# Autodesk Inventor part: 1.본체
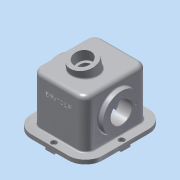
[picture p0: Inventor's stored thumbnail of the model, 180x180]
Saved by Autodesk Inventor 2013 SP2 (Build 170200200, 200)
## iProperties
Created: 2014-11
Part Number: 1.본체
Material: 알루미늄 6061
Document SubType Name: Modeling
Designer: dgall
Density: 2.71 g/cm^3
Mass: 2882.1 g
Surface Area: 2079.78 cm^2
Volume: 1063.5 cm^3
Author: dgall
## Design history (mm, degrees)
sketch "스케치1"
  geometry: L1 (-87, 98)-(87, 98); L2 (87, 98)-(87, -98); L3 (87, -98)-(-87, -98); L4 (-87, -98)-(-87, 98); 3 further points
  constraints: 8 end point, 2 midpoint, 2 parallel, 1 horizontal, 1 horizontal alignment, 1 perpendicular, 1 vertical alignment
  dimensions: "d0" = 196 distance of L1.end L2.end; "d2" = 174 distance of L2.end L3.end
extrude "돌출1" new body sketch "스케치1" distance "d3" = 10; taper "d4" = 0 deg
sketch "스케치2"
  geometry: L1 (65, -0.8)-(65, 118); L2 (65, 118)-(-65, 118); L3 (-65, 118)-(-65, -0.8); L4 (-87, 0)-(87, 0) reference; L5 (-65, -0.8)-(65, -0.8); 3 further points
  constraints: 8 end point, 2 midpoint, 2 perpendicular, 1 parallel, 1 vertical, 1 vertical alignment
  dimensions: "d5" = 130 distance of L1.end L2.end; "d7" = 118 distance between parallel lines of L2 L4
extrude "돌출2" join sketch "스케치2" stored distance "d8" = 152; taper "d9" = 0 deg
node "작업 평면2"
sketch "스케치4"
  geometry: L1 (98, 0)-(-98, 0) reference; L2 (98, -10)-(-98, -10) reference; C1 r 45.5 at (0, 58); 2 further points
  constraints: 2 vertical alignment, 1 centre point, 1 midpoint
  dimensions: "d11" = 68 distance from line of C1.centre L2; "d12" = 91 diameter of C1
extrude "돌출3" join sketch "스케치4" stored distance "d13" = 152; taper "d14" = 0 deg
node "작업 평면3"
sketch "스케치5"
  geometry: L1 (-98, -10)-(98, -10) reference; L2 (-98, 0)-(98, 0) reference; L3 (-66, -10)-(-66, 108); L4 (-66, 108)-(66, 108); L5 (66, 108)-(66, -10); L6 (76, 0)-(76, 118) reference; L7 (76, 118)-(-76, 118) reference; 3 further points
  constraints: 6 end point, 2 midpoint, 2 perpendicular, 2 point on line, 1 horizontal, 1 parallel, 1 vertical alignment
  dimensions: "d16" = 10 distance between parallel lines of L6 L5; "d17" = 10 distance between parallel lines of L7 L4
extrude "돌출4" cut sketch "스케치5" stored distance "d18" = 110; taper "d19" = 0 deg
sketch "스케치6"
  geometry: L1 (55, 108)-(55, -10) reference; L2 (-55, -10)-(55, -10) reference; L3 (55, 103.5)-(45, 93.5); L4 (45, 93.5)-(45, 58); L5 (45, 58)-(55, 58); 1 further point
  constraints: 6 end point, 2 point on line, 1 horizontal, 1 perpendicular
  dimensions: "d31" = 68 distance between parallel lines of L5 L2; "d32" = 71 diameter of L3.end L5; "d33" = 91 diameter of L3.start L5; "d34" = 10 horizontal distance of L3.start L3.end
revolve "회전1" sketch "스케치6" stored, may be unused: angle "d35" = 90 deg
sketch "스케치7"
  geometry: C1 r 45.5 at (0, 0) reference; C2 r 26 at (0, 0); 1 further point
  constraints: 1 centre point, 1 coincident
  dimensions: "d36" = 52 diameter of C2
extrude "돌출5" cut sketch "스케치7" stored distance "d38" = 110; taper "d39" = 0 deg
node "작업 평면4"
node "작업 평면6"
  node "작업 평면5"
sketch "스케치8"
  geometry: L1 (0, -45.5)-(0, 45.5) reference; L2 (164, -107.917)-(-10, -107.917) reference; C1 r 31 at (77, 0); 3 further points
  constraints: 2 midpoint, 1 centre point, 1 coincident, 1 horizontal alignment, 1 vertical alignment
  dimensions: "d42" = 62 diameter of C1
extrude "돌출6" join sketch "스케치8" stored distance "d44" = 110; taper "d45" = 0 deg
sketch "스케치9"
  geometry: C1 r 31 at (0, 0) reference; C2 r 21 at (0, 0)
  constraints: 1 centre point, 1 coincident
  dimensions: "d46" = 42 diameter of C2
extrude "돌출7" cut sketch "스케치9" distance "d48" = 25; taper "d49" = 0 deg
sketch "스케치10"
  geometry: C1 r 21 at (0, 0) reference; C2 r 15 at (0, 0)
  constraints: 1 centre point, 1 coincident
  dimensions: "d50" = 30 diameter of C2
extrude "돌출8" cut sketch "스케치10" stored distance "d52" = 25; taper "d53" = 0 deg
node "작업 평면7"
sketch "스케치11"
  geometry: C1 r 26 at (0, 0) reference; C2 r 45.5 at (0, 0) reference; A1 r 35 centre (0, 0) between (35, 0) and (0, 35); 3 further points
  constraints: 4 point on circle, 2 horizontal alignment, 2 vertical alignment, 1 centre point, 1 coincident
  dimensions: "d54" = 70 diameter of A1
hole "구멍1" sketch "스케치11" at (35, 0), (0, 35), (0, -35), (-35, 0) diameter "d56" = 3.242; stored, may be unused: countersink angle "d60" = 90 deg, drill point angle "d62" = 118 deg; dims "d57" = 13, "d58" = 4, "d59" = 2, "d61" = 16
node "작업 평면8"
sketch "스케치12"
  geometry: L1 (87, 98)-(-87, 98) reference; L2 (87, -98)-(87, 98) reference; L3 (11, 98)-(11, 78); L4 (11, 78)-(-11, 78); L5 (-11, 78)-(-11, 98); 2 further points
  constraints: 6 end point, 2 perpendicular, 2 point on line, 1 midpoint, 1 parallel, 1 vertical alignment
  dimensions: "d64" = 20 distance of L4.end L5.end; "d66" = 22 distance of L3.end L4.end
extrude "돌출9" join sketch "스케치12" distance "d67" = 5; taper "d68" = 0 deg
sketch "스케치13"
  geometry: L1 (-87, 98)-(-87, -98) reference; L2 (87, -98)-(87, 98) reference; L3 (55, -66)-(-55, -66) reference; L4 (87, -11)-(67, -11); L5 (67, -11)-(67, 11); L6 (67, 11)-(87, 11); L7 (-87, -11)-(-67, -11); L8 (-67, -11)-(-67, 11); L9 (-67, 11)-(-87, 11); 3 further points
  constraints: 12 end point, 4 perpendicular, 4 point on line, 2 horizontal alignment, 2 midpoint, 1 horizontal, 1 parallel
  dimensions: "d70" = 22 distance of L4.end L5.end; "d72" = 20 distance of L5.end L6.end; "d73" = 22 distance of L7.end L8.end; "d74" = 20 distance of L8.end L9.end
extrude "돌출10" join sketch "스케치13" distance "d75" = 5; taper "d76" = 0 deg
fillet "모깎기2" dims "d78" = 20
fillet "모깎기3" dims "d79" = 10
fillet "모깎기4" dims "d80" = 42
fillet "모깎기5" dims "d81" = 3
fillet "모깎기6" dims "d82" = 3
fillet "모깎기7" dims "d83" = 3
fillet "모깎기8" dims "d84" = 3
chamfer "모따기1" distance "d85" = 1; stored, may be unused: second distance "d86" = 2, angle "d87" = 45 deg
node "작업 평면9"
sketch "스케치17"
  geometry: L1 (-45, 98)-(45, 98) reference; L2 (-87, -56)-(-87, 56) reference; L3 (45, -98)-(-45, -98) reference; L4 (87, 56)-(87, -56) reference; C1 r 7 at (0, 88); C2 r 7 at (0, -88); C3 r 7 at (77, 0); C4 r 7 at (-77, 0); 1 further point
  constraints: 4 centre point, 3 equal radius, 2 horizontal alignment, 2 vertical alignment
  dimensions: "d88" = 14 diameter of C3; "d90" = 10 distance from line of L4 C3.centre; "d91" = 10 distance from line of L2 C4.centre; "d92" = 10 distance from line of L3 C2.centre; "d93" = 10 distance from line of L1 C1.centre
extrude "돌출11" cut sketch "스케치17" distance "d94" = 8.6; taper "d95" = 0 deg
sketch "스케치18"
  geometry: C1 r 7 at (0, 0) reference; C2 r 4.5 at (0, 0); C3 r 7 at (0, -176) reference; C4 r 4.5 at (0, -176); C5 r 7 at (77, -88) reference; C6 r 7 at (-77, -88) reference; C7 r 4.5 at (-77, -88); C8 r 4.5 at (77, -88); 1 further point
  constraints: 4 centre point, 4 coincident, 3 equal radius
  dimensions: "d96" = 9 diameter of C2
extrude "돌출12" cut sketch "스케치18" stored distance "d98" = 8.6; taper "d99" = 0 deg
fillet "모깎기9" dims "d100" = 10
fillet "모깎기10" dims "d101" = 3
sketch "스케치19"
  geometry: L1 (45, 118)-(-45, 118) reference; L2 (45, -10)-(11, -10) reference; 3 further points
  constraints: 1 midpoint, 1 vertical alignment, 1 other
  dimensions: "d102" = 92 distance from line of point (0, 82) L2
feature "엠보싱1" sketch "스케치19" dims "d103" = 1, "d104" = 0
node "솔리드1"
mirror "대칭1"
mirror "대칭2"
mirror "대칭3"
mirror "대칭4"
mirror "대칭5"
node "작업축1"
node "작업 평면10"
other parameters: "d10" = -77, "d15" = 0, "d40" = -78 deg, "d41" = 86
